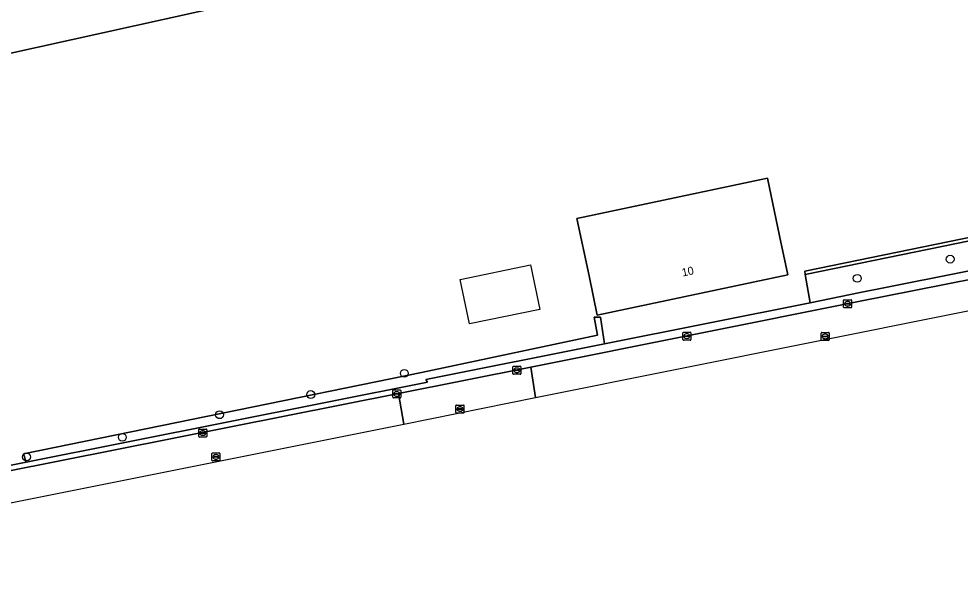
# Model space of a CAD drawing. Extents: x 161477 to 163040, y 383680 to 384871.
# Drawn here: x 162394.9 to 162512.5, y 383810.4 to 383881.8 of the extents above; entities that cross this region are included whole.
import ezdxf

# ---------------------------------------------------------------- set-up
doc = ezdxf.new("R2010")
doc.units = 0
for name, color, linetype in [('IMGEO_Boom', 7, 'Continuous'), ('IMGEO_Erf', 7, 'Continuous'), ('IMGEO_Groenvoorziening', 7, 'Continuous'), ('IMGEO_Haag', 7, 'Continuous'), ('IMGEO_Kolk', 7, 'Continuous'), ('IMGEO_Pand', 7, 'Continuous'), ('IMGEO_Pand_nummerreeks', 7, 'Continuous'), ('IMGEO_Pand_vergunning_verleend', 7, 'Continuous'), ('IMGEO_Rijbaan_lokaal_open', 7, 'Continuous'), ('IMGEO_Rioolput', 7, 'Continuous'), ('IMGEO_Voetpad_open', 7, 'Continuous')]:
    doc.layers.add(name, color=color, linetype=linetype)

msp = doc.modelspace()

# ---------------------------------------------------------------- linework, layer by layer
at = {"layer": 'IMGEO_Boom'}
for centre in [(162511.23, 383851.73), (162499.62, 383849.34), (162443.03, 383837.48), (162431.34, 383834.82), (162419.94, 383832.3), (162407.79, 383829.48), (162395.82, 383827.03)]:
    msp.add_circle(centre, 0.489, dxfattribs=at)
at = {"layer": 'IMGEO_Erf'}
for points in [[(162421.56, 383883.57), (162312.05, 383859.38), (162312.37, 383857.91), (162254.76, 383845.19), (162254.46, 383846.53), (162253.68, 383850.09), (162222.78, 383843.26)], [(162319.15, 383811.08), (162380.16, 383823.26), (162395.79, 383826.38), (162395.46, 383827.41), (162445.16, 383837.56), (162467.17, 383842.24), (162466.76, 383844.47), (162467.52, 383844.47), (162468.05, 383841.17), (162493.72, 383846.3), (162493.13, 383849.82), (162493.06, 383850.22), (162529, 383857.59)]]:
    msp.add_lwpolyline(points, dxfattribs=at)
msp.add_lwpolyline([(162466.11, 383849.64), (162464.6, 383856.83), (162488.41, 383861.84), (162489.92, 383854.65), (162490.95, 383849.76), (162467.14, 383844.74)], close=True, dxfattribs=at)
at = {"layer": 'IMGEO_Groenvoorziening'}
for points in [[(162529.1, 383857.2), (162529, 383857.59), (162493.06, 383850.22), (162493.13, 383849.82)], [(162468.05, 383841.17), (162467.52, 383844.47), (162466.76, 383844.47), (162467.17, 383842.24), (162445.16, 383837.56), (162395.46, 383827.41), (162395.79, 383826.38), (162445.92, 383836.39), (162445.73, 383836.7)]]:
    msp.add_lwpolyline(points, close=True, dxfattribs=at)
msp.add_lwpolyline([(162529.26, 383856.52), (162529.1, 383857.2), (162493.13, 383849.82), (162493.72, 383846.3), (162500, 383847.56), (162502.95, 383848.15), (162522.58, 383852.07)], dxfattribs=at)
at = {"layer": 'IMGEO_Haag'}
for points in [[(162529.1, 383857.2), (162529, 383857.59), (162493.06, 383850.22), (162493.13, 383849.82)], [(162445.92, 383836.39), (162445.73, 383836.7), (162468.05, 383841.17), (162467.52, 383844.47), (162466.76, 383844.47), (162467.17, 383842.24), (162445.16, 383837.56), (162395.46, 383827.41), (162395.79, 383826.38)]]:
    msp.add_lwpolyline(points, close=True, dxfattribs=at)
at = {"layer": 'IMGEO_Kolk'}
for p, q in [((162497.92, 383845.73), (162497.92, 383846.59)), ((162497.99, 383846.66), (162498.85, 383846.66)), ((162498.18, 383846.15), (162498.18, 383846.17)), ((162498.22, 383846.2), (162498.62, 383846.2)), ((162498.61, 383846.12), (162498.22, 383846.12)), ((162498.43, 383845.88), (162498.4, 383845.88)), ((162498.41, 383846.44), (162498.43, 383846.44)), ((162498.66, 383846.17), (162498.66, 383846.15)), ((162498.92, 383846.59), (162498.92, 383845.73)), ((162498.85, 383845.66), (162497.99, 383845.66)), ((162477.83, 383841.69), (162477.83, 383842.54)), ((162477.91, 383842.62), (162478.76, 383842.62)), ((162478.32, 383842.4), (162478.34, 383842.4)), ((162478.83, 383842.54), (162478.83, 383841.69)), ((162478.76, 383841.62), (162477.91, 383841.62)), ((162478.09, 383842.11), (162478.09, 383842.12)), ((162478.13, 383842.16), (162478.53, 383842.16)), ((162478.53, 383842.07), (162478.13, 383842.07)), ((162478.34, 383841.84), (162478.32, 383841.84)), ((162478.57, 383842.12), (162478.57, 383842.11)), ((162456.6, 383837.43), (162456.6, 383838.28)), ((162456.67, 383838.36), (162457.53, 383838.36)), ((162456.86, 383837.85), (162456.86, 383837.86)), ((162456.9, 383837.9), (162457.3, 383837.9)), ((162457.3, 383837.81), (162456.9, 383837.81)), ((162457.11, 383837.58), (162457.08, 383837.58)), ((162457.09, 383838.14), (162457.11, 383838.14)), ((162457.34, 383837.86), (162457.34, 383837.85)), ((162457.6, 383838.28), (162457.6, 383837.43)), ((162457.53, 383837.36), (162456.67, 383837.36)), ((162441.59, 383834.48), (162441.59, 383835.33)), ((162441.66, 383835.4), (162442.52, 383835.4)), ((162442.08, 383835.18), (162442.1, 383835.18)), ((162442.59, 383835.33), (162442.59, 383834.48)), ((162442.52, 383834.4), (162441.66, 383834.4)), ((162441.85, 383834.9), (162441.85, 383834.91)), ((162441.89, 383834.95), (162442.29, 383834.95)), ((162442.29, 383834.86), (162441.89, 383834.86)), ((162442.1, 383834.62), (162442.08, 383834.62)), ((162442.33, 383834.91), (162442.33, 383834.9)), ((162417.41, 383830.51), (162418.27, 383830.51)), ((162417.34, 383829.58), (162417.34, 383830.44)), ((162418.27, 383829.51), (162417.41, 383829.51)), ((162417.6, 383830), (162417.6, 383830.02)), ((162417.64, 383830.05), (162418.04, 383830.05)), ((162418.04, 383829.97), (162417.64, 383829.97)), ((162417.85, 383829.73), (162417.82, 383829.73)), ((162417.83, 383830.29), (162417.85, 383830.29)), ((162418.08, 383830.02), (162418.08, 383830)), ((162418.34, 383830.44), (162418.34, 383829.58))]:
    msp.add_line(p, q, dxfattribs=at)
for points in [[(162497.92, 383845.73), (162497.92, 383846.59)], [(162497.99, 383846.66), (162498.85, 383846.66)], [(162498.92, 383846.59), (162498.92, 383845.73)], [(162498.85, 383845.66), (162497.99, 383845.66)], [(162477.83, 383841.69), (162477.83, 383842.54)], [(162477.91, 383842.62), (162478.76, 383842.62)], [(162478.83, 383842.54), (162478.83, 383841.69)], [(162478.76, 383841.62), (162477.91, 383841.62)], [(162456.6, 383837.43), (162456.6, 383838.28)], [(162456.67, 383838.36), (162457.53, 383838.36)], [(162457.6, 383838.28), (162457.6, 383837.43)], [(162457.53, 383837.36), (162456.67, 383837.36)], [(162441.59, 383834.48), (162441.59, 383835.33)], [(162441.66, 383835.4), (162442.52, 383835.4)], [(162442.59, 383835.33), (162442.59, 383834.48)], [(162442.52, 383834.4), (162441.66, 383834.4)], [(162417.41, 383830.51), (162418.27, 383830.51)], [(162417.34, 383829.58), (162417.34, 383830.44)], [(162418.27, 383829.51), (162417.41, 383829.51)], [(162418.34, 383830.44), (162418.34, 383829.58)]]:
    msp.add_lwpolyline(points, dxfattribs=at)
for centre, radius, start, end in [((162497.99, 383846.59), 0.0765, 91.552, 178.448), ((162497.99, 383846.59), 0.0765, 91.552, 178.448), ((162497.99, 383845.74), 0.0765, 181.552, 268.448), ((162497.99, 383845.74), 0.0765, 181.552, 268.448), ((162498.22, 383846.16), 0.0403, 85.8775, 175.7526), ((162498.21, 383846.15), 0.0366, 178.938, 274.7102), ((162498.62, 383846.16), 0.043, 264.8664, 352.4533), ((162498.62, 383846.17), 0.0386, 1.7309, 96.639), ((162498.84, 383846.59), 0.0765, 1.552, 88.448), ((162498.84, 383846.59), 0.0765, 1.552, 88.448), ((162498.84, 383845.74), 0.0765, 271.552, 358.448), ((162498.84, 383845.74), 0.0765, 271.552, 358.448), ((162477.91, 383842.54), 0.0765, 91.552, 178.448), ((162477.91, 383842.54), 0.0765, 91.552, 178.448), ((162478.76, 383842.54), 0.0765, 1.552, 88.448), ((162478.76, 383842.54), 0.0765, 1.552, 88.448), ((162477.91, 383841.69), 0.0765, 181.552, 268.448), ((162477.91, 383841.69), 0.0765, 181.552, 268.448), ((162478.13, 383842.12), 0.0403, 85.8775, 175.7526), ((162478.13, 383842.11), 0.0366, 178.938, 274.7102), ((162478.54, 383842.12), 0.0386, 1.7309, 96.639), ((162478.53, 383842.12), 0.043, 264.8664, 352.4533), ((162478.76, 383841.69), 0.0765, 271.552, 358.448), ((162478.76, 383841.69), 0.0765, 271.552, 358.448), ((162456.68, 383838.28), 0.0765, 91.552, 178.448), ((162456.68, 383838.28), 0.0765, 91.552, 178.448), ((162456.9, 383837.86), 0.0403, 85.8775, 175.7526), ((162456.89, 383837.85), 0.0366, 178.938, 274.7102), ((162457.3, 383837.86), 0.0386, 1.7309, 96.639), ((162457.3, 383837.86), 0.043, 264.8664, 352.4533), ((162457.52, 383838.28), 0.0765, 1.552, 88.448), ((162457.52, 383838.28), 0.0765, 1.552, 88.448), ((162456.68, 383837.43), 0.0765, 181.552, 268.448), ((162456.68, 383837.43), 0.0765, 181.552, 268.448), ((162457.52, 383837.43), 0.0765, 271.552, 358.448), ((162457.52, 383837.43), 0.0765, 271.552, 358.448), ((162441.67, 383835.33), 0.0765, 91.552, 178.448), ((162441.67, 383835.33), 0.0765, 91.552, 178.448), ((162442.51, 383835.33), 0.0765, 1.552, 88.448), ((162442.51, 383835.33), 0.0765, 1.552, 88.448), ((162441.67, 383834.48), 0.0765, 181.552, 268.448), ((162441.67, 383834.48), 0.0765, 181.552, 268.448), ((162441.89, 383834.91), 0.0403, 85.8775, 175.7526), ((162441.89, 383834.9), 0.0366, 178.938, 274.7102), ((162442.29, 383834.91), 0.0386, 1.7309, 96.639), ((162442.29, 383834.9), 0.043, 264.8664, 352.4533), ((162442.51, 383834.48), 0.0765, 271.552, 358.448), ((162442.51, 383834.48), 0.0765, 271.552, 358.448), ((162417.42, 383830.43), 0.0765, 91.552, 178.448), ((162417.42, 383830.43), 0.0765, 91.552, 178.448), ((162418.26, 383830.43), 0.0765, 1.552, 88.448), ((162418.26, 383830.43), 0.0765, 1.552, 88.448), ((162417.42, 383829.59), 0.0765, 181.552, 268.448), ((162417.42, 383829.59), 0.0765, 181.552, 268.448), ((162417.64, 383830.01), 0.0403, 85.8775, 175.7526), ((162417.63, 383830), 0.0366, 178.938, 274.7102), ((162418.04, 383830.01), 0.0386, 1.7309, 96.639), ((162418.04, 383830.01), 0.043, 264.8664, 352.4533), ((162418.26, 383829.59), 0.0765, 271.552, 358.448), ((162418.26, 383829.59), 0.0765, 271.552, 358.448)]:
    msp.add_arc(centre, radius, start, end, dxfattribs=at)
for centre, major_axis, ratio, start_param, end_param in [((162498.41, 383846.16), (-0.387, 0.002), 0.722429, 4.712389, 7.853982), ((162498.43, 383846.16), (-0.39, 0.002), 0.717154, 1.570796, 4.712389), ((162478.32, 383842.12), (-0.387, 0.002), 0.722429, 4.712389, 7.853982), ((162478.34, 383842.12), (-0.39, 0.002), 0.717154, 1.570796, 4.712389), ((162457.09, 383837.86), (-0.387, 0.002), 0.722429, 4.712389, 7.853982), ((162457.11, 383837.86), (-0.39, 0.002), 0.717154, 1.570796, 4.712389), ((162442.08, 383834.9), (-0.387, 0.002), 0.722429, 4.712389, 7.853982), ((162442.1, 383834.9), (-0.39, 0.002), 0.717154, 1.570796, 4.712389), ((162417.83, 383830.01), (-0.387, 0.002), 0.722429, 4.712389, 7.853982), ((162417.85, 383830.01), (-0.39, 0.002), 0.717154, 1.570796, 4.712389)]:
    msp.add_ellipse(centre, major_axis=major_axis, ratio=ratio, start_param=start_param, end_param=end_param, dxfattribs=at)
at = {"layer": 'IMGEO_Pand'}
for points in [[(162304.96, 383877.5), (162250.29, 383865.42), (162249.55, 383868.79), (162223.78, 383863.1), (162218.56, 383861.94), (162222.78, 383843.26), (162253.68, 383850.09), (162254.46, 383846.53), (162254.76, 383845.19), (162312.37, 383857.91), (162312.05, 383859.38), (162421.56, 383883.57), (162417.41, 383902.34), (162405.62, 383899.74), (162402.4, 383899.03)], [(162467.14, 383844.74), (162490.95, 383849.76), (162489.92, 383854.65), (162488.41, 383861.84), (162464.6, 383856.83), (162466.11, 383849.64)]]:
    msp.add_lwpolyline(points, close=True, dxfattribs=at)
at = {"layer": 'IMGEO_Pand_vergunning_verleend'}
msp.add_lwpolyline([(162450.02, 383849.21), (162458.8, 383851.01), (162459.94, 383845.44), (162451.16, 383843.65)], close=True, dxfattribs=at)
at = {"layer": 'IMGEO_Rijbaan_lokaal_open'}
for points in [[(162526.28, 383851.82), (162522.11, 383850.88), (162503.15, 383847.1), (162500, 383846.47), (162458.82, 383838.26), (162459.43, 383834.44), (162511.58, 383844.89), (162607.29, 383864.04)], [(162525.93, 383852.81), (162522.58, 383852.07), (162502.95, 383848.15), (162500, 383847.56), (162493.72, 383846.3), (162468.05, 383841.17), (162445.73, 383836.7), (162445.92, 383836.39), (162395.79, 383826.38), (162380.16, 383823.26), (162319.15, 383811.08)], [(162500, 383846.47), (162503.15, 383847.1), (162522.11, 383850.88), (162526.28, 383851.82)], [(162318.95, 383810.39), (162319.24, 383810.45), (162379.65, 383822.47), (162380.32, 383822.6), (162393.08, 383825.15), (162442.31, 383834.97), (162458.82, 383838.26), (162500, 383846.47)], [(162442.97, 383831.14), (162459.43, 383834.44), (162458.82, 383838.26), (162442.31, 383834.97), (162442.97, 383831.14)]]:
    msp.add_lwpolyline(points, dxfattribs=at)
at = {"layer": 'IMGEO_Rioolput'}
for p, q in [((162495.11, 383841.66), (162495.11, 383842.51)), ((162495.19, 383842.58), (162496.04, 383842.58)), ((162495.6, 383842.36), (162495.63, 383842.36)), ((162496.12, 383842.51), (162496.12, 383841.66)), ((162496.04, 383841.58), (162495.19, 383841.58)), ((162495.37, 383842.08), (162495.37, 383842.09)), ((162495.81, 383842.04), (162495.41, 383842.04)), ((162495.42, 383842.13), (162495.81, 383842.13)), ((162495.62, 383841.8), (162495.6, 383841.8)), ((162495.86, 383842.09), (162495.86, 383842.08)), ((162449.48, 383832.59), (162449.48, 383833.44)), ((162449.56, 383833.51), (162450.41, 383833.51)), ((162449.74, 383833.01), (162449.74, 383833.02)), ((162450.18, 383832.97), (162449.78, 383832.97)), ((162449.79, 383833.06), (162450.18, 383833.06)), ((162449.97, 383833.29), (162450, 383833.29)), ((162450.23, 383833.02), (162450.23, 383833.01)), ((162450.48, 383833.44), (162450.48, 383832.59)), ((162450.41, 383832.51), (162449.56, 383832.51)), ((162449.99, 383832.73), (162449.97, 383832.73)), ((162418.99, 383826.61), (162418.99, 383827.46)), ((162419.06, 383827.54), (162419.92, 383827.54)), ((162419.25, 383827.03), (162419.25, 383827.04)), ((162419.29, 383827.08), (162419.69, 383827.08)), ((162419.69, 383826.99), (162419.29, 383826.99)), ((162419.48, 383827.32), (162419.5, 383827.32)), ((162419.73, 383827.04), (162419.73, 383827.03)), ((162419.99, 383827.46), (162419.99, 383826.61)), ((162419.92, 383826.54), (162419.06, 383826.54)), ((162419.5, 383826.76), (162419.47, 383826.76))]:
    msp.add_line(p, q, dxfattribs=at)
for points in [[(162495.11, 383841.66), (162495.11, 383842.51)], [(162495.19, 383842.58), (162496.04, 383842.58)], [(162496.12, 383842.51), (162496.12, 383841.66)], [(162496.04, 383841.58), (162495.19, 383841.58)], [(162449.48, 383832.59), (162449.48, 383833.44)], [(162449.56, 383833.51), (162450.41, 383833.51)], [(162450.48, 383833.44), (162450.48, 383832.59)], [(162450.41, 383832.51), (162449.56, 383832.51)], [(162418.99, 383826.61), (162418.99, 383827.46)], [(162419.06, 383827.54), (162419.92, 383827.54)], [(162419.99, 383827.46), (162419.99, 383826.61)], [(162419.92, 383826.54), (162419.06, 383826.54)]]:
    msp.add_lwpolyline(points, dxfattribs=at)
for centre, radius, start, end in [((162495.19, 383842.51), 0.0765, 91.552, 178.448), ((162495.19, 383842.51), 0.0765, 91.552, 178.448), ((162496.04, 383842.51), 0.0765, 1.552, 88.448), ((162496.04, 383842.51), 0.0765, 1.552, 88.448), ((162495.19, 383841.66), 0.0765, 181.552, 268.448), ((162495.19, 383841.66), 0.0765, 181.552, 268.448), ((162495.41, 383842.09), 0.0403, 85.8775, 175.7526), ((162495.41, 383842.08), 0.0366, 178.938, 274.7102), ((162495.82, 383842.09), 0.0386, 1.7309, 96.639), ((162495.81, 383842.08), 0.043, 264.8664, 352.4533), ((162496.04, 383841.66), 0.0765, 271.552, 358.448), ((162496.04, 383841.66), 0.0765, 271.552, 358.448), ((162449.56, 383833.44), 0.0765, 91.552, 178.448), ((162449.56, 383833.44), 0.0765, 91.552, 178.448), ((162449.78, 383833.02), 0.0403, 85.8775, 175.7526), ((162449.78, 383833.01), 0.0366, 178.938, 274.7102), ((162450.19, 383833.02), 0.0386, 1.7309, 96.639), ((162450.18, 383833.01), 0.043, 264.8664, 352.4533), ((162450.41, 383833.44), 0.0765, 1.552, 88.448), ((162450.41, 383833.44), 0.0765, 1.552, 88.448), ((162449.56, 383832.59), 0.0765, 181.552, 268.448), ((162449.56, 383832.59), 0.0765, 181.552, 268.448), ((162450.41, 383832.59), 0.0765, 271.552, 358.448), ((162450.41, 383832.59), 0.0765, 271.552, 358.448), ((162419.07, 383827.46), 0.0765, 91.552, 178.448), ((162419.07, 383827.46), 0.0765, 91.552, 178.448), ((162419.29, 383827.04), 0.0403, 85.8775, 175.7526), ((162419.28, 383827.03), 0.0366, 178.938, 274.7102), ((162419.69, 383827.04), 0.0386, 1.7309, 96.639), ((162419.69, 383827.04), 0.043, 264.8664, 352.4533), ((162419.91, 383827.46), 0.0765, 1.552, 88.448), ((162419.91, 383827.46), 0.0765, 1.552, 88.448), ((162419.07, 383826.61), 0.0765, 181.552, 268.448), ((162419.07, 383826.61), 0.0765, 181.552, 268.448), ((162419.91, 383826.61), 0.0765, 271.552, 358.448), ((162419.91, 383826.61), 0.0765, 271.552, 358.448)]:
    msp.add_arc(centre, radius, start, end, dxfattribs=at)
for centre, major_axis, ratio, start_param, end_param in [((162495.6, 383842.08), (-0.387, 0.002), 0.722429, 4.712389, 7.853982), ((162495.63, 383842.08), (-0.39, 0.002), 0.717154, 1.570796, 4.712389), ((162449.97, 383833.01), (-0.387, 0.002), 0.722429, 4.712389, 7.853982), ((162449.99, 383833.01), (-0.39, 0.002), 0.717154, 1.570796, 4.712389), ((162419.48, 383827.04), (-0.387, 0.002), 0.722429, 4.712389, 7.853982), ((162419.5, 383827.04), (-0.39, 0.002), 0.717154, 1.570796, 4.712389)]:
    msp.add_ellipse(centre, major_axis=major_axis, ratio=ratio, start_param=start_param, end_param=end_param, dxfattribs=at)
at = {"layer": 'IMGEO_Voetpad_open'}
msp.add_lwpolyline([(162393.83, 383821.29), (162442.97, 383831.14), (162442.31, 383834.97), (162393.08, 383825.15)], close=True, dxfattribs=at)

# ---------------------------------------------------------------- texts
at = {"layer": 'IMGEO_Pand_nummerreeks'}
msp.add_text('10', height=1, rotation=11.8844, dxfattribs=at).set_placement((162477.81, 383849.56))

doc.saveas('drawing.dxf')
